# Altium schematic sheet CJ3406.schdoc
size 127 x 101 mm
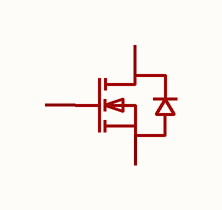
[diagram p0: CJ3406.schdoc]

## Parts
Q?  cj3406  [SOT-23-3_L2.9-W1.6-P1.90-LS2.8-BR]  (value not drawn)

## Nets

Not connected (* = marked no-connect by the designer): Q? 1(G) 2(S) 3(D)

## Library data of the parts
Q? = cj3406: 数量:1个N沟道;漏源电压(Vdss):30V;连续漏极电流(Id):3.6A;导通电阻(RDS(on)):65mΩ@10V;耗散功率(Pd):350mW;阈值电压(Vgs(th)):1V;; Manufacturer: CJ(江苏长电/长晶); AddInBom: yes; ModelId: 89cb27a44ab2466697082bb9fd73a7d0; ModelName: SOT-23-3L_L2.9-W1.6-H1.1-LS2.8-P0.95; ModelTransform: 114.173,110.236,0,90,0,0,0,0,0; Number: 1个N沟道; Drain to Source Voltage: 30V; Current - Continuous Drain(Id): 3.6A; Pd - Power Dissipation: 350mW; Gate Threshold Voltage (Vgs(th)): 1V; Input Capacitance(Ciss): 375pF; Reverse Transfer Capacitance (Crss@Vds): 39pF; Type: N沟道; Output Capacitance(Coss): 57pF; Vgs: ±20V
